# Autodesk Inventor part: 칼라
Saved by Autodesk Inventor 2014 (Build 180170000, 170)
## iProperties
Created: 2024-08
Part Number: 칼라
Material: 일반
Document SubType Name: Modeling
Designer: dg
Density: 1 g/cm^3
Appearance: 기본값
Author: dg
Author: jhkim
Creation Date: 2024-08-09
Sending System: Autodesk Inventor 2025
Preprocessor: ST-DEVELOPER v20
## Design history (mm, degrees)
node "칼라1"
node "솔리드1"
node "기준1"
